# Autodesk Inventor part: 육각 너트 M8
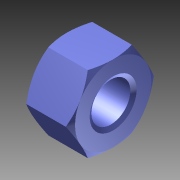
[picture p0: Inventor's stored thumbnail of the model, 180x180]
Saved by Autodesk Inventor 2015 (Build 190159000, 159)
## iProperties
Created: 2024-12
Part Number: 육각 너트 M8
Material: 일반
Document SubType Name: Modeling
Designer: 102566
Density: 1 g/cm^3
Appearance: 기본값
Author: 102566
Author: jhkim
Description: 6각 너트 및 6각 가는 너트
Creation Date: 2024-11-28
Sending System: Autodesk Inventor 2025
Preprocessor: ST-DEVELOPER v20
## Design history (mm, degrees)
node "육각 너트 M81"
body "Solid1"
node "기준1"
